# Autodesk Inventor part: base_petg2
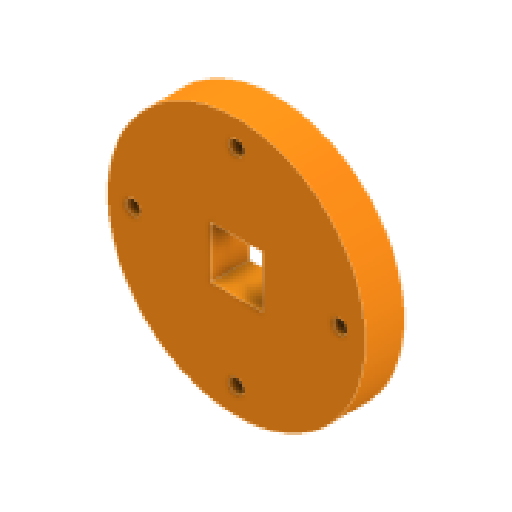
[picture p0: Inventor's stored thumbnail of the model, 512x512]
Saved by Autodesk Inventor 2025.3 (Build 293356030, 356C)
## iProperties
Created: 2025-09
Part Number: base_petg2
Material: Plastica PET
Document SubType Name: Modeling
Designer: Ryzen5700u
Density: 1.541 g/cm^3
Appearance: Arancione
Author: Ryzen5700u
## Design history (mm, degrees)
sketch "Schizzo1"
  geometry: C1 r 50 at (0, 0); 1 further point
  constraints: 1 centre point, 1 coincident
  dimensions: "d0" = 100 diameter of C1
extrude "Estrusione1" new body sketch "Schizzo1" distance "d1" = 15; taper "d2" = 0 deg
sketch "Schizzo2"
  geometry: 2 further points
  dimensions: "d3" = 40 distance of point (0, 0) point (0, 40)
hole "Foro1" sketch "Schizzo2" at (0, 40) diameter "d4" = 5.5; stored, may be unused: countersink angle "d8" = 90 deg, drill point angle "d10" = 118 deg; dims "d5" = 6, "d6" = 9, "d7" = 4, "d9" = 8
pattern_circular "Serie circolare1" dims angle "d12" = 360 deg
sketch "Schizzo5"
  geometry: L1 (10.05, 10.05)-(-10.05, 10.05); L2 (-10.05, 10.05)-(-10.05, -10.05); L3 (-10.05, -10.05)-(10.05, -10.05); L4 (10.05, -10.05)-(10.05, 10.05); L5 (10.05, 10.05)-(-10.05, -10.05); L6 (-10.05, 10.05)-(10.05, -10.05); 1 further point
  constraints: 12 end point, 2 midpoint, 2 parallel, 1 horizontal, 1 perpendicular
  dimensions: "d27" = 20.1 distance of L3.end L2.end; "d28" = 20.1 distance of L2.end L1.end
extrude "Estrusione3" cut sketch "Schizzo5" extent not by distance; stored distance "d29" = 0; taper "d30" = 0 deg
node "Solido1"
